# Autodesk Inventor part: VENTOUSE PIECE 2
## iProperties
Created: 2004-11
Part Number: VENTOUSE PIECE 2
Document SubType Name: Modeling
Designer: Bruno
Manufacturer: Standard
Standards Organization: Custom
Author: Bruno
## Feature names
1. Base1
